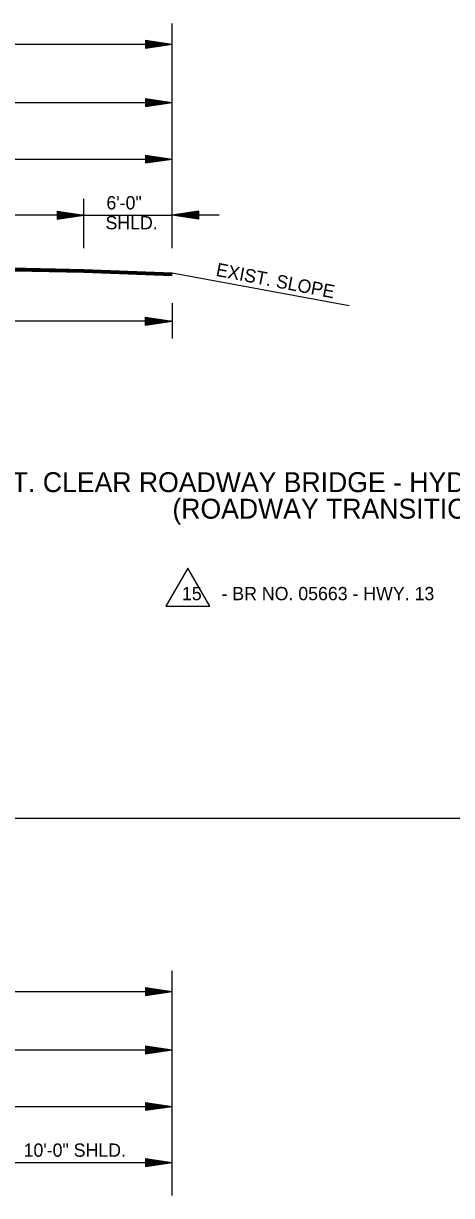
# Model space of a CAD drawing. Extents: x 549600 to 1930787, y -1955432 to 596640.
# Drawn here: x 551438 to 551680, y -1952647 to -1951984 of the extents above; entities that cross this region are included whole.
import ezdxf

# ---------------------------------------------------------------- set-up
doc = ezdxf.new("R2010")
doc.units = 0
doc.layers.add('R_Border', color=7, linetype='Continuous')
doc.layers.add('S_AREA_CALC', color=7, linetype='Continuous')

msp = doc.modelspace()

# ---------------------------------------------------------------- linework, layer by layer
at = {"layer": 'R_Border'}
for p, q in [((551518.53, -1952313.61), (551543.33, -1952313.61)), ((551008.97, -1952433.38), (552070.24, -1952433.38))]:
    msp.add_line(p, q, dxfattribs=at)
msp.add_lwpolyline([(551543.33, -1952313.61), (551530.93, -1952292.13), (551518.53, -1952313.61)], dxfattribs=at)
at = {"layer": 'S_AREA_CALC'}
for p, q in [((551522.02, -1952111.3), (551522.02, -1951984.26)), ((551182.02, -1951995.93), (551522.02, -1951995.93)), ((551507.02, -1951993.68), (551522.02, -1951995.93)), ((551507.02, -1951993.68), (551507.02, -1951998.18)), ((551507.02, -1951994.06), (551519.51, -1951995.93)), ((551507.02, -1951994.44), (551516.93, -1951995.93)), ((551507.02, -1951994.82), (551514.44, -1951995.93)), ((551507.02, -1951995.21), (551511.89, -1951995.93)), ((551507.02, -1951995.58), (551509.39, -1951995.93)), ((551507.02, -1951998.18), (551522.02, -1951995.93)), ((551507.02, -1951996.67), (551511.89, -1951995.93)), ((551507.02, -1951997.43), (551516.93, -1951995.93)), ((551507.02, -1951997.81), (551519.51, -1951995.93)), ((551507.02, -1951997.05), (551514.44, -1951995.93)), ((551507.02, -1951996.29), (551509.39, -1951995.93)), ((551182.02, -1952028.9), (551522.02, -1952028.9)), ((551507.02, -1952026.65), (551522.02, -1952028.9)), ((551507.02, -1952026.65), (551507.02, -1952031.15)), ((551507.02, -1952027.02), (551519.51, -1952028.9)), ((551507.02, -1952027.41), (551516.93, -1952028.9)), ((551507.02, -1952027.78), (551514.44, -1952028.9)), ((551507.02, -1952028.17), (551511.89, -1952028.9)), ((551507.02, -1952028.55), (551509.39, -1952028.9)), ((551507.02, -1952031.15), (551522.02, -1952028.9)), ((551507.02, -1952029.63), (551511.89, -1952028.9)), ((551507.02, -1952030.39), (551516.93, -1952028.9)), ((551507.02, -1952030.77), (551519.51, -1952028.9)), ((551507.02, -1952030.02), (551514.44, -1952028.9)), ((551507.02, -1952029.25), (551509.39, -1952028.9)), ((551182.02, -1952060.87), (551522.02, -1952060.87)), ((551507.02, -1952058.62), (551522.02, -1952060.87)), ((551507.02, -1952058.62), (551507.02, -1952063.12)), ((551507.02, -1952059), (551519.51, -1952060.87)), ((551507.02, -1952059.38), (551516.93, -1952060.87)), ((551507.02, -1952059.76), (551514.44, -1952060.87)), ((551507.02, -1952060.15), (551511.89, -1952060.87)), ((551507.02, -1952060.52), (551509.39, -1952060.87)), ((551507.02, -1952063.12), (551522.02, -1952060.87)), ((551507.02, -1952061.61), (551511.89, -1952060.87)), ((551507.02, -1952062.37), (551516.93, -1952060.87)), ((551507.02, -1952062.75), (551519.51, -1952060.87)), ((551507.02, -1952061.99), (551514.44, -1952060.87)), ((551507.02, -1952061.23), (551509.39, -1952060.87)), ((551472.02, -1952111.3), (551472.02, -1952083.34)), ((551457.02, -1952090.28), (551472.02, -1952092.53)), ((551457.02, -1952090.28), (551457.02, -1952094.78)), ((551537.02, -1952090.28), (551522.02, -1952092.53)), ((551537.02, -1952090.28), (551537.02, -1952094.78)), ((551472.02, -1952092.53), (551352.02, -1952092.53)), ((551457.02, -1952090.66), (551469.51, -1952092.53)), ((551457.02, -1952091.04), (551466.93, -1952092.53)), ((551457.02, -1952091.42), (551464.44, -1952092.53)), ((551457.02, -1952091.81), (551461.89, -1952092.53)), ((551457.02, -1952092.18), (551459.39, -1952092.53)), ((551457.02, -1952094.78), (551472.02, -1952092.53)), ((551457.02, -1952093.27), (551461.89, -1952092.53)), ((551457.02, -1952094.03), (551466.93, -1952092.53)), ((551457.02, -1952094.41), (551469.51, -1952092.53)), ((551457.02, -1952093.65), (551464.44, -1952092.53)), ((551457.02, -1952092.89), (551459.39, -1952092.53)), ((551472.02, -1952092.53), (551522.02, -1952092.53)), ((551537.02, -1952094.78), (551522.02, -1952092.53)), ((551548.54, -1952092.53), (551522.02, -1952092.53)), ((551537.02, -1952090.66), (551524.52, -1952092.53)), ((551537.02, -1952094.41), (551524.52, -1952092.53)), ((551537.02, -1952091.04), (551527.1, -1952092.53)), ((551537.02, -1952094.03), (551527.1, -1952092.53)), ((551537.02, -1952091.42), (551529.6, -1952092.53)), ((551537.02, -1952093.65), (551529.6, -1952092.53)), ((551537.02, -1952091.81), (551532.14, -1952092.53)), ((551537.02, -1952093.27), (551532.14, -1952092.53)), ((551537.02, -1952092.18), (551534.65, -1952092.53)), ((551537.02, -1952092.89), (551534.65, -1952092.53)), ((551352.02, -1952120.84), (551472.02, -1952123.24)), ((551352.02, -1952121.14), (551472.02, -1952123.54)), ((551352.02, -1952121.44), (551472.02, -1952123.84)), ((551352.02, -1952121.74), (551472.02, -1952124.14)), ((551352.02, -1952122.04), (551472.02, -1952124.44)), ((551352.02, -1952122.34), (551472.02, -1952124.74)), ((551352.02, -1952122.51), (551472.02, -1952124.91)), ((551472.02, -1952123.24), (551522.02, -1952125.24)), ((551472.02, -1952123.54), (551522.02, -1952125.54)), ((551472.02, -1952123.84), (551522.02, -1952125.84)), ((551472.02, -1952124.14), (551522.02, -1952126.14)), ((551472.02, -1952124.44), (551522.02, -1952126.44)), ((551472.02, -1952124.74), (551522.02, -1952126.74)), ((551522.02, -1952125.24), (551622.09, -1952143.62)), ((551522.02, -1952142.25), (551522.02, -1952162.25)), ((551522.02, -1952152.5), (551182.02, -1952152.5)), ((551507.02, -1952150.25), (551522.02, -1952152.5)), ((551507.02, -1952154.75), (551507.02, -1952150.25)), ((551507.02, -1952150.63), (551519.51, -1952152.5)), ((551507.02, -1952151.01), (551516.93, -1952152.5)), ((551507.02, -1952151.38), (551514.44, -1952152.5)), ((551507.02, -1952151.77), (551511.89, -1952152.5)), ((551507.02, -1952152.15), (551509.39, -1952152.5)), ((551507.02, -1952154.75), (551522.02, -1952152.5)), ((551507.02, -1952153.23), (551511.89, -1952152.5)), ((551507.02, -1952153.99), (551516.93, -1952152.5)), ((551507.02, -1952154.38), (551519.51, -1952152.5)), ((551507.02, -1952153.62), (551514.44, -1952152.5)), ((551507.02, -1952152.85), (551509.39, -1952152.5)), ((551522.02, -1952646.64), (551522.02, -1952519.6)), ((551122.02, -1952531.28), (551522.02, -1952531.28)), ((551507.02, -1952529.03), (551522.02, -1952531.28)), ((551507.02, -1952529.03), (551507.02, -1952533.53)), ((551507.02, -1952529.4), (551519.51, -1952531.28)), ((551507.02, -1952529.78), (551516.93, -1952531.28)), ((551507.02, -1952530.16), (551514.44, -1952531.28)), ((551507.02, -1952530.55), (551511.89, -1952531.28)), ((551507.02, -1952530.92), (551509.39, -1952531.28)), ((551507.02, -1952533.53), (551522.02, -1952531.28)), ((551507.02, -1952532.01), (551511.89, -1952531.28)), ((551507.02, -1952532.77), (551516.93, -1952531.28)), ((551507.02, -1952533.15), (551519.51, -1952531.28)), ((551507.02, -1952532.39), (551514.44, -1952531.28)), ((551507.02, -1952531.63), (551509.39, -1952531.28)), ((551122.02, -1952564.24), (551522.02, -1952564.24)), ((551507.02, -1952561.99), (551522.02, -1952564.24)), ((551507.02, -1952561.99), (551507.02, -1952566.49)), ((551507.02, -1952562.37), (551519.51, -1952564.24)), ((551507.02, -1952562.75), (551516.93, -1952564.24)), ((551507.02, -1952563.12), (551514.44, -1952564.24)), ((551507.02, -1952563.51), (551511.89, -1952564.24)), ((551507.02, -1952563.89), (551509.39, -1952564.24)), ((551507.02, -1952566.49), (551522.02, -1952564.24)), ((551507.02, -1952564.98), (551511.89, -1952564.24)), ((551507.02, -1952565.73), (551516.93, -1952564.24)), ((551507.02, -1952566.12), (551519.51, -1952564.24)), ((551507.02, -1952565.36), (551514.44, -1952564.24)), ((551507.02, -1952564.59), (551509.39, -1952564.24)), ((551122.02, -1952596.22), (551522.02, -1952596.22)), ((551507.02, -1952593.97), (551522.02, -1952596.22)), ((551507.02, -1952593.97), (551507.02, -1952598.47)), ((551507.02, -1952594.34), (551519.51, -1952596.22)), ((551507.02, -1952594.72), (551516.93, -1952596.22)), ((551507.02, -1952595.1), (551514.44, -1952596.22)), ((551507.02, -1952595.49), (551511.89, -1952596.22)), ((551507.02, -1952595.86), (551509.39, -1952596.22)), ((551507.02, -1952598.47), (551522.02, -1952596.22)), ((551507.02, -1952596.95), (551511.89, -1952596.22)), ((551507.02, -1952597.71), (551516.93, -1952596.22)), ((551507.02, -1952598.09), (551519.51, -1952596.22)), ((551507.02, -1952597.33), (551514.44, -1952596.22)), ((551507.02, -1952596.57), (551509.39, -1952596.22)), ((551507.02, -1952625.63), (551522.02, -1952627.88)), ((551507.02, -1952625.63), (551507.02, -1952630.13)), ((551507.02, -1952626), (551519.51, -1952627.88)), ((551507.02, -1952626.38), (551516.93, -1952627.88)), ((551507.02, -1952626.76), (551514.44, -1952627.88)), ((551422.02, -1952627.88), (551522.02, -1952627.88)), ((551507.02, -1952627.15), (551511.89, -1952627.88)), ((551507.02, -1952627.52), (551509.39, -1952627.88)), ((551507.02, -1952630.13), (551522.02, -1952627.88)), ((551507.02, -1952628.61), (551511.89, -1952627.88)), ((551507.02, -1952629.37), (551516.93, -1952627.88)), ((551507.02, -1952629.75), (551519.51, -1952627.88)), ((551507.02, -1952628.99), (551514.44, -1952627.88)), ((551507.02, -1952628.23), (551509.39, -1952627.88))]:
    msp.add_line(p, q, dxfattribs=at)

# ---------------------------------------------------------------- texts
at = {"layer": 'R_Border'}
for s, height, p in [('28 FT. CLEAR ROADWAY BRIDGE - HYDRODEMOLITION', 11.25, (551401.23, -1952249.12)), ('(ROADWAY TRANSITIONS)', 11.25, (551522.18, -1952264.12)), ('15', 7.5, (551527.57, -1952310.2)), ('- BR NO. 05663 - HWY. 13', 7.5, (551549.93, -1952310.2))]:
    msp.add_text(s, height=height, dxfattribs=at).set_placement(p)
at = {"layer": 'S_AREA_CALC'}
for s, p in [('6\'-0"', (551484.84, -1952089.36)), ('SHLD.', (551484.34, -1952100.61)), ('10\'-0" SHLD.', (551438, -1952624.71))]:
    msp.add_text(s, height=7.5, dxfattribs=at).set_placement(p)
msp.add_text('EXIST. SLOPE', height=7.5, rotation=349.11714, dxfattribs=at).set_placement((551546.4, -1952126.84))

doc.saveas('drawing.dxf')
